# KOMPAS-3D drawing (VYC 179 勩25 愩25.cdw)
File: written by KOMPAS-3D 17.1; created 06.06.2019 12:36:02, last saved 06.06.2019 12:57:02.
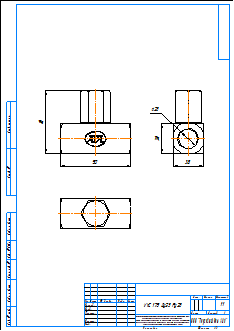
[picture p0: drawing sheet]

Sheet 1: A3, portrait

Title block, sheet 1: name: VYC 179 Ду25 Ру25; material: Внимание! Данный продукт является объектом авторского права ООО «Торговый Дом АДЛ». / Запрещается изменение, копирование, распространение / (в том числе путем копирования на другие сайты и ресурсы в Интернете) / или любое иное использование информации и объектов без предварительного / согласия правообладателя (ООО «Торговый Дом АДЛ»).; sheets: 1; organisation: ООО "Торговый дом АДЛ"; sheet format: A3; stored path: \\adlc.lan\data\АДЛ_ПКД\3D-модели\Поставщики\VYC Industrial\VYC 179\KOMPAS 2D\VYC 179 Ду25 Ру25.cdw

Views: Вид 1, Проекционный вид 2, Проекционный вид 3
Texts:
  user
Dimensions and other numbers on the sheet: 90; 81; 38; 25; 1:1; 1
